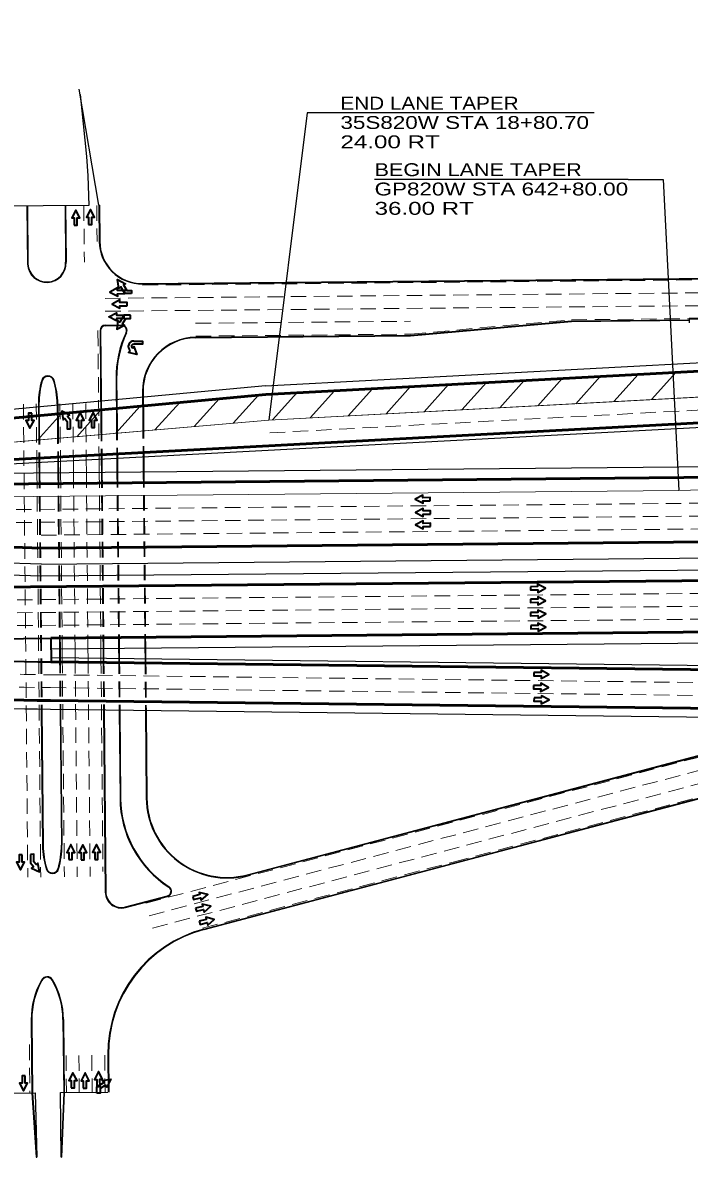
# Model space of a CAD drawing. Extents: x 2326434 to 2368642, y 6985225 to 6995090.
# Drawn here: x 2330793 to 2331414, y 6990716 to 6991772 of the extents above; entities that cross this region are included whole.
import ezdxf

# ---------------------------------------------------------------- set-up
doc = ezdxf.new("R2010")
doc.units = 0
doc.header["$LTSCALE"] = 4.8
doc.linetypes.add('MEDIUM_DASHED', pattern=[4.5, 3, -1.5])
for name, color, linetype, lineweight in [('10', 7, 'Continuous', 35), ('26', 7, 'Continuous', 25), ('27', 7, 'Continuous', 25), ('28', 7, 'Continuous', 25), ('40', 7, 'Continuous', 35), ('5', 7, 'Continuous', 25), ('50', 7, 'MEDIUM_DASHED', 13)]:
    doc.layers.add(name, color=color, linetype=linetype, lineweight=lineweight)

msp = doc.modelspace()

# ---------------------------------------------------------------- linework, layer by layer
at = {"layer": '10'}
for p, q in [((2330426.072, 6991195.246), (2330819.65, 6991198.923)), ((2330819.65, 6991198.923), (2330819.856, 6991176.858))]:
    msp.add_line(p, q, dxfattribs=at)
for centre, radius, start, end in [((2331921.237, 6992748.984), 1265.239, 273.05017, 273.05017), ((2330888.37, 6996870.024), 5693.578, 265.34266, 269.30964)]:
    msp.add_arc(centre, radius, start, end, dxfattribs=at)
at = {"layer": '26'}
for p, q in [((2330723.193, 6991352.028), (2332252.211, 6991366.314)), ((2330810.967, 6991256.844), (2332091.911, 6991268.812)), ((2330819.743, 6991188.923), (2332235.248, 6991202.148))]:
    msp.add_line(p, q, dxfattribs=at)
at = {"layer": '26', "lineweight": 53}
for p, q in [((2330723.287, 6991342.029), (2332252.305, 6991356.314)), ((2330686.071, 6991245.677), (2332092.005, 6991258.812)), ((2330819.65, 6991198.923), (2332235.154, 6991212.148))]:
    msp.add_line(p, q, dxfattribs=at)
at = {"layer": '27'}
for p, q in [((2331413.972, 6991496.376), (2331414.01, 6991492.377)), ((2331019.444, 6991433.897), (2331988.561, 6991485.537)), ((2330723.061, 6991358.019), (2332517.722, 6991453.649)), ((2331019.444, 6991433.897), (2330720.507, 6991405.951)), ((2330819.818, 6991180.859), (2332703.156, 6991158.166))]:
    msp.add_line(p, q, dxfattribs=at)
at = {"layer": '27', "lineweight": 53}
for p, q in [((2331019.869, 6991425.908), (2331988.987, 6991477.549)), ((2330723.1, 6991362.027), (2332517.509, 6991457.643)), ((2330720.933, 6991397.962), (2331019.869, 6991425.908)), ((2330819.77, 6991176.859), (2332703.108, 6991154.166)), ((2330819.337, 6991140.862), (2331786.164, 6991129.212))]:
    msp.add_line(p, q, dxfattribs=at)
at = {"layer": '27'}
msp.add_lwpolyline([(2330819.23, 6991132.863), (2331565.86, 6991123.866), (2331786.067, 6991121.213)], dxfattribs=at)
at = {"layer": '27', "lineweight": 40}
msp.add_arc((2331440.616, 6988645.712), 2850.789, 83.98494, 90.53549, dxfattribs=at)
at = {"layer": '27', "lineweight": 53}
msp.add_arc((2330888.37, 6996870.024), 5729.578, 265.33564, 269.30964, dxfattribs=at)
at = {"layer": '27'}
msp.add_arc((2330888.37, 6996870.024), 5737.578, 265.48726, 269.30964, dxfattribs=at)
at = {"layer": '28'}
for p, q in [((2330864.386, 6991601.901), (2330846.071, 6991710.103)), ((2330854.998, 6991601.813), (2330764.308, 6991600.966)), ((2330797.388, 6991601.275), (2330797.893, 6991547.239)), ((2330797.888, 6991601.28), (2330798.393, 6991547.243)), ((2330832.887, 6991601.607), (2330833.379, 6991548.944)), ((2330833.387, 6991601.611), (2330833.879, 6991548.949)), ((2330864.885, 6991601.906), (2330864.386, 6991601.901)), ((2330864.386, 6991601.901), (2330864.7, 6991568.246)), ((2330864.885, 6991601.906), (2330865.2, 6991568.251)), ((2330905.067, 6991529.122), (2331710.807, 6991536.652)), ((2330905.072, 6991528.622), (2331710.811, 6991536.152)), ((2331304.39, 6991494.352), (2331413.982, 6991495.376)), ((2331304.414, 6991493.852), (2331413.986, 6991494.876)), ((2330865.476, 6991485.25), (2330866.303, 6991396.692)), ((2330865.976, 6991485.254), (2330866.803, 6991396.722)), ((2330870.429, 6991490.296), (2330885.56, 6991490.438)), ((2330870.433, 6991489.796), (2330885.564, 6991489.938)), ((2331154.508, 6991480.951), (2331304.39, 6991494.352)), ((2331154.533, 6991480.451), (2331304.414, 6991493.852)), ((2330954.537, 6991479.082), (2331154.508, 6991480.951)), ((2330954.542, 6991478.582), (2331154.533, 6991480.451)), ((2330880.396, 6991440.387), (2330880.796, 6991397.58)), ((2330880.896, 6991440.392), (2330881.295, 6991397.611)), ((2330905.007, 6991428.617), (2330905.282, 6991399.164)), ((2330905.507, 6991428.621), (2330905.782, 6991399.169)), ((2330808.11, 6991417.049), (2330808.33, 6991393.51)), ((2330808.61, 6991417.054), (2330808.83, 6991393.535)), ((2330825.61, 6991417.213), (2330825.823, 6991394.408)), ((2330826.11, 6991417.217), (2330826.323, 6991394.434)), ((2330808.62, 6991362.578), (2330808.711, 6991352.827)), ((2330809.119, 6991362.605), (2330809.211, 6991352.832)), ((2330826.112, 6991363.51), (2330826.21, 6991352.991)), ((2330826.612, 6991363.537), (2330826.71, 6991352.996)), ((2330866.593, 6991365.667), (2330866.708, 6991353.369)), ((2330867.093, 6991365.694), (2330867.208, 6991353.374)), ((2330881.087, 6991366.439), (2330881.208, 6991353.505)), ((2330881.586, 6991366.466), (2330881.707, 6991353.509)), ((2330905.576, 6991367.744), (2330905.706, 6991353.734)), ((2330906.075, 6991367.771), (2330906.206, 6991353.738)), ((2330810.865, 6991267.844), (2330385.724, 6991280.873)), ((2330810.865, 6991267.844), (2331441.837, 6991273.739)), ((2330385.827, 6991269.873), (2330810.967, 6991256.844)), ((2330827.743, 6991188.998), (2330827.82, 6991180.763)), ((2330828.243, 6991189.003), (2330828.32, 6991180.757)), ((2330868.241, 6991189.376), (2330868.326, 6991180.275)), ((2330868.741, 6991189.381), (2330868.826, 6991180.269)), ((2330882.74, 6991189.512), (2330882.828, 6991180.1)), ((2330883.24, 6991189.517), (2330883.328, 6991180.094)), ((2330907.239, 6991189.741), (2330907.332, 6991179.805)), ((2330907.739, 6991189.745), (2330907.832, 6991179.799)), ((2330810.765, 6991132.983), (2330811.953, 6991005.934)), ((2330811.265, 6991132.976), (2330812.453, 6991005.939)), ((2330828.268, 6991132.755), (2330829.452, 6991006.097)), ((2330828.768, 6991132.749), (2330829.952, 6991006.102)), ((2330868.774, 6991132.266), (2330870.361, 6990962.531)), ((2330869.275, 6991132.26), (2330870.861, 6990962.536)), ((2330883.277, 6991132.091), (2330884.046, 6991049.749)), ((2330883.777, 6991132.085), (2330884.546, 6991049.754)), ((2330907.781, 6991131.796), (2330908.545, 6991049.978)), ((2330908.281, 6991131.79), (2330909.045, 6991049.983)), ((2331002.577, 6990978.652), (2331426.947, 6991090.806)), ((2331002.705, 6990978.169), (2331427.074, 6991090.322)), ((2331194.544, 6990989.047), (2331436.911, 6991053.1)), ((2330962.238, 6990927.652), (2331194.544, 6990989.047)), ((2330889.065, 6990948.653), (2330928.215, 6990958.999)), ((2330889.193, 6990948.169), (2330928.343, 6990958.516)), ((2330801.47, 6990843.524), (2330802.105, 6990775.581)), ((2330801.97, 6990843.529), (2330802.605, 6990775.586)), ((2330830.969, 6990843.8), (2330831.604, 6990775.868)), ((2330831.469, 6990843.805), (2330832.104, 6990775.873)), ((2330872.777, 6990810.997), (2330873.101, 6990776.272)), ((2330873.277, 6990811.002), (2330873.601, 6990776.277)), ((2330802.105, 6990775.581), (2330806.065, 6990715.617)), ((2330802.604, 6990775.614), (2330806.565, 6990715.622)), ((2330828.775, 6990775.841), (2330872.601, 6990776.267)), ((2330829.181, 6990715.867), (2330828.775, 6990775.841)), ((2330831.604, 6990775.893), (2330829.181, 6990715.867)), ((2330832.104, 6990775.873), (2330829.68, 6990715.847)), ((2330806.065, 6990715.617), (2330806.565, 6990715.622)), ((2330829.18, 6990715.842), (2330829.68, 6990715.847))]:
    msp.add_line(p, q, dxfattribs=at)
at = {"layer": '28', "linetype": 'MEDIUM_DASHED'}
for p, q in [((2330808.33, 6991393.51), (2330808.62, 6991362.578)), ((2330808.83, 6991393.535), (2330809.119, 6991362.605)), ((2330825.823, 6991394.408), (2330826.112, 6991363.51)), ((2330826.323, 6991394.434), (2330826.612, 6991363.537)), ((2330866.303, 6991396.692), (2330866.593, 6991365.667)), ((2330866.803, 6991396.722), (2330867.093, 6991365.694)), ((2330880.796, 6991397.58), (2330881.087, 6991366.439)), ((2330881.295, 6991397.611), (2330881.586, 6991366.466)), ((2330905.282, 6991399.164), (2330905.576, 6991367.744)), ((2330905.782, 6991399.197), (2330906.075, 6991367.771)), ((2330808.711, 6991352.827), (2330810.765, 6991132.983)), ((2330809.211, 6991352.832), (2330811.265, 6991132.976)), ((2330826.21, 6991352.991), (2330827.743, 6991188.998)), ((2330826.71, 6991352.996), (2330828.243, 6991189.003)), ((2330866.708, 6991353.369), (2330868.241, 6991189.376)), ((2330867.208, 6991353.374), (2330868.741, 6991189.381)), ((2330881.208, 6991353.505), (2330882.74, 6991189.512)), ((2330881.707, 6991353.509), (2330883.24, 6991189.517)), ((2330905.706, 6991353.734), (2330907.239, 6991189.741)), ((2330906.206, 6991353.738), (2330907.739, 6991189.745)), ((2330827.82, 6991180.763), (2330828.268, 6991132.755)), ((2330828.32, 6991180.757), (2330828.768, 6991132.749)), ((2330868.326, 6991180.275), (2330868.774, 6991132.266)), ((2330868.826, 6991180.269), (2330869.275, 6991132.26)), ((2330882.828, 6991180.1), (2330883.277, 6991132.091)), ((2330883.328, 6991180.094), (2330883.777, 6991132.085)), ((2330907.332, 6991179.805), (2330907.781, 6991131.796)), ((2330907.832, 6991179.799), (2330908.281, 6991131.79))]:
    msp.add_line(p, q, dxfattribs=at)
at = {"layer": '28', "lineweight": 53}
msp.add_line((2330810.724, 6991282.843), (2330510.625, 6991292.04), dxfattribs=at)
at = {"layer": '28'}
for points in [[(2330846.906, 6991705.171), (2330852.935, 6991647.371), (2330853.974, 6991629.26), (2330854.998, 6991601.813)], [(2330962.11, 6990928.135), (2331194.416, 6990989.53), (2331436.784, 6991053.584)], [(2330773.606, 6990775.304), (2330805.132, 6990775.611), (2330806.565, 6990715.622)]]:
    msp.add_lwpolyline(points, dxfattribs=at)
at = {"layer": '28', "lineweight": 53}
msp.add_lwpolyline([(2330810.724, 6991282.843), (2331791.682, 6991292.008), (2332091.556, 6991306.81)], dxfattribs=at)
at = {"layer": '28'}
for centre, radius, start, end in [((2330904.698, 6991568.62), 40, 180.53544, 270.53549), ((2330904.698, 6991568.62), 39.5, 180.53544, 270.53549), ((2330815.872, 6991548.093), 18, 182.78276, 2.78276), ((2330815.872, 6991548.093), 17.5, 182.78276, 2.78276), ((2330870.475, 6991485.296), 5, 90.53549, 180.53544), ((2330870.475, 6991485.296), 4.5, 90.53549, 180.53544), ((2330885.606, 6991485.438), 5, 335.15854, 90.53549), ((2330885.606, 6991485.438), 4.5, 335.15854, 90.53549), ((2330980.891, 6991441.326), 100.5, 155.15854, 180.53544), ((2330980.891, 6991441.326), 100, 155.15854, 180.53544), ((2330955.004, 6991429.084), 50, 90.53549, 180.53544), ((2330955.004, 6991429.084), 49.5, 90.53549, 180.53544), ((2330816.918, 6991437.184), 6, 17.50561, 163.59031), ((2330816.918, 6991437.184), 5.5, 17.50561, 163.59031), ((2330883.108, 6991417.691), 75, 163.59031, 180.49039), ((2330883.108, 6991417.691), 74.5, 163.59031, 180.49039), ((2330751.114, 6991416.429), 74.5, 0.58018, 17.50561), ((2330751.114, 6991416.429), 75, 0.58018, 17.50561), ((2330983.542, 6991050.679), 99.5, 180.53544, 237.10882), ((2330983.542, 6991050.679), 99, 180.53544, 237.10882), ((2330983.542, 6991050.679), 75, 180.53544, 284.80383), ((2330983.542, 6991050.679), 74.5, 180.53544, 284.80383), ((2330886.949, 6991006.634), 75, 180.53512, 197.49281), ((2330886.949, 6991006.634), 74.5, 180.53512, 197.49281), ((2330754.955, 6991005.401), 74.5, 343.5777, 0.53544), ((2330754.955, 6991005.401), 75, 343.5777, 0.53544), ((2330821.14, 6990985.894), 6, 197.49281, 343.5777), ((2330821.14, 6990985.894), 5.5, 197.49281, 343.5777), ((2330927.065, 6990963.35), 4.5, 284.80383, 57.10882), ((2330927.065, 6990963.35), 5, 284.80383, 57.10882), ((2330885.36, 6990962.671), 15, 180.53544, 284.80383), ((2330885.36, 6990962.671), 14.5, 180.53544, 284.80383), ((2330992.772, 6990812.119), 120, 104.80383, 180.53544), ((2330992.772, 6990812.119), 119.5, 104.80383, 180.53544), ((2330816.135, 6990877.707), 6, 30.15527, 150.97153), ((2330816.135, 6990877.707), 5.5, 30.15527, 150.97153), ((2330876.467, 6990844.225), 75, 150.97153, 180.53544), ((2330876.467, 6990844.225), 74.5, 150.97153, 180.53544), ((2330756.473, 6990843.045), 74.5, 0.58018, 30.15527), ((2330756.473, 6990843.045), 75, 0.58018, 30.15527)]:
    msp.add_arc(centre, radius, start, end, dxfattribs=at)
at = {"layer": '40'}
for points in [[(2330841.307, 6991583.527), (2330844.308, 6991583.527), (2330844.308, 6991590.334), (2330846.745, 6991590.334), (2330842.966, 6991597.534), (2330839.187, 6991590.334), (2330841.307, 6991590.334)], [(2330854.848, 6991584.034), (2330857.849, 6991584.034), (2330857.849, 6991590.84), (2330860.286, 6991590.84), (2330856.507, 6991598.04), (2330852.728, 6991590.84), (2330854.848, 6991590.84)], [(2330894.652, 6991519.716), (2330888.668, 6991519.695), (2330884.811, 6991526.054), (2330882.805, 6991524.669), (2330881.825, 6991532.742), (2330889.025, 6991528.963), (2330887.281, 6991527.759), (2330890.425, 6991522.669), (2330894.603, 6991522.745)], [(2330888.668, 6991519.695), (2330888.601, 6991522.695), (2330881.796, 6991522.543), (2330881.742, 6991524.98), (2330874.627, 6991521.041), (2330881.91, 6991517.424), (2330881.863, 6991519.543)], [(2330890.715, 6991508.387), (2330890.713, 6991511.388), (2330883.906, 6991511.383), (2330883.904, 6991513.82), (2330876.707, 6991510.037), (2330883.909, 6991506.263), (2330883.908, 6991508.382)], [(2330887.681, 6991499.626), (2330887.671, 6991496.625), (2330880.864, 6991496.65), (2330880.855, 6991494.212), (2330873.669, 6991498.017), (2330880.882, 6991501.77), (2330880.875, 6991499.65)], [(2330893.665, 6991499.716), (2330887.681, 6991499.626), (2330883.944, 6991493.196), (2330881.913, 6991494.543), (2330881.083, 6991486.454), (2330888.212, 6991490.366), (2330886.445, 6991491.538), (2330889.494, 6991496.685), (2330893.673, 6991496.688)], [(2330801.878, 6991408.46), (2330798.877, 6991408.46), (2330798.877, 6991401.653), (2330796.44, 6991401.653), (2330800.219, 6991394.453), (2330803.998, 6991401.653), (2330801.878, 6991401.653)], [(2330838.005, 6991393.883), (2330837.908, 6991401.826), (2330835.147, 6991405.234), (2330837.1, 6991406.692), (2330829.765, 6991410.202), (2330831.044, 6991402.171), (2330832.742, 6991403.439), (2330834.92, 6991400.751), (2330835.005, 6991393.846)], [(2330845.291, 6991395.043), (2330848.291, 6991395.043), (2330848.291, 6991401.849), (2330850.729, 6991401.849), (2330846.95, 6991409.05), (2330843.171, 6991401.849), (2330845.291, 6991401.849)], [(2330857.434, 6991395.031), (2330860.435, 6991395.031), (2330860.435, 6991401.837), (2330862.872, 6991401.837), (2330859.093, 6991409.037), (2330855.314, 6991401.837), (2330857.434, 6991401.837)], [(2331172.901, 6991326.836), (2331172.852, 6991329.836), (2331166.046, 6991329.724), (2331166.006, 6991332.161), (2331158.869, 6991328.264), (2331166.13, 6991324.604), (2331166.095, 6991326.723)], [(2331173.038, 6991314.452), (2331172.989, 6991317.452), (2331166.183, 6991317.34), (2331166.143, 6991319.777), (2331159.006, 6991315.879), (2331166.268, 6991312.22), (2331166.233, 6991314.339)], [(2331173.115, 6991302.865), (2331173.065, 6991305.865), (2331166.259, 6991305.753), (2331166.219, 6991308.19), (2331159.082, 6991304.293), (2331166.344, 6991300.634), (2331166.309, 6991302.753)], [(2331266.034, 6991246.823), (2331266.086, 6991243.823), (2331272.892, 6991243.941), (2331272.935, 6991241.505), (2331280.068, 6991245.408), (2331272.803, 6991249.061), (2331272.84, 6991246.942)], [(2331266.121, 6991235.237), (2331266.173, 6991232.237), (2331272.979, 6991232.355), (2331273.021, 6991229.918), (2331280.155, 6991233.822), (2331272.89, 6991237.475), (2331272.927, 6991235.355)], [(2331266.27, 6991222.853), (2331266.322, 6991219.852), (2331273.128, 6991219.971), (2331273.17, 6991217.534), (2331280.303, 6991221.438), (2331273.038, 6991225.091), (2331273.075, 6991222.971)], [(2331266.371, 6991210.739), (2331266.423, 6991207.739), (2331273.229, 6991207.858), (2331273.272, 6991205.421), (2331280.405, 6991209.324), (2331273.14, 6991212.977), (2331273.177, 6991210.858)], [(2331269.245, 6991167.006), (2331269.19, 6991164.005), (2331275.996, 6991163.881), (2331275.951, 6991161.444), (2331283.219, 6991165.091), (2331276.089, 6991169.001), (2331276.05, 6991166.882)], [(2331268.914, 6991154.896), (2331268.86, 6991151.896), (2331275.665, 6991151.772), (2331275.621, 6991149.335), (2331282.889, 6991152.982), (2331275.759, 6991156.891), (2331275.72, 6991154.772)], [(2331269.453, 6991143.364), (2331269.399, 6991140.363), (2331276.204, 6991140.239), (2331276.16, 6991137.802), (2331283.428, 6991141.449), (2331276.298, 6991145.359), (2331276.259, 6991143.24)], [(2330836.542, 6990992.738), (2330839.543, 6990992.738), (2330839.543, 6990999.545), (2330841.98, 6990999.545), (2330838.202, 6991006.745), (2330834.423, 6990999.545), (2330836.542, 6990999.545)], [(2330847.792, 6990992.65), (2330850.793, 6990992.65), (2330850.793, 6990999.457), (2330853.23, 6990999.457), (2330849.451, 6991006.657), (2330845.672, 6990999.457), (2330847.792, 6990999.457)], [(2330860.497, 6990992.87), (2330863.498, 6990992.87), (2330863.498, 6990999.676), (2330865.935, 6990999.676), (2330862.157, 6991006.877), (2330858.378, 6990999.676), (2330860.497, 6990999.676)], [(2330793.116, 6990997.343), (2330790.115, 6990997.343), (2330790.115, 6990990.537), (2330787.678, 6990990.537), (2330791.457, 6990983.337), (2330795.235, 6990990.537), (2330793.116, 6990990.537)], [(2330800.713, 6990997.653), (2330800.81, 6990989.71), (2330803.571, 6990986.302), (2330801.617, 6990984.844), (2330808.952, 6990981.334), (2330807.674, 6990989.365), (2330805.976, 6990988.097), (2330803.798, 6990990.785), (2330803.713, 6990997.69)], [(2330951.78, 6990958.519), (2330952.516, 6990955.61), (2330959.115, 6990957.281), (2330959.713, 6990954.918), (2330965.765, 6990960.349), (2330957.858, 6990962.245), (2330958.378, 6990960.19)], [(2330954.456, 6990947.592), (2330955.193, 6990944.683), (2330961.791, 6990946.354), (2330962.389, 6990943.991), (2330968.442, 6990949.422), (2330960.534, 6990951.318), (2330961.055, 6990949.263)], [(2330957.788, 6990935.329), (2330958.524, 6990932.42), (2330965.123, 6990934.091), (2330965.721, 6990931.728), (2330971.773, 6990937.159), (2330963.866, 6990939.055), (2330964.386, 6990937)], [(2330795.861, 6990791.566), (2330792.861, 6990791.566), (2330792.861, 6990784.759), (2330790.423, 6990784.759), (2330794.202, 6990777.559), (2330797.981, 6990784.759), (2330795.861, 6990784.759)], [(2330838.611, 6990780.219), (2330841.612, 6990780.219), (2330841.612, 6990787.026), (2330844.049, 6990787.026), (2330840.271, 6990794.226), (2330836.492, 6990787.026), (2330838.611, 6990787.026)], [(2330849.861, 6990780.132), (2330852.862, 6990780.132), (2330852.862, 6990786.938), (2330855.299, 6990786.938), (2330851.52, 6990794.139), (2330847.741, 6990786.938), (2330849.861, 6990786.938)], [(2330862.554, 6990781.376), (2330865.554, 6990781.446), (2330865.395, 6990788.251), (2330867.832, 6990788.308), (2330863.887, 6990795.418), (2330860.277, 6990788.132), (2330862.396, 6990788.181)], [(2330862.581, 6990775.392), (2330862.554, 6990781.376), (2330868.909, 6990785.239), (2330867.523, 6990787.244), (2330875.594, 6990788.232), (2330871.822, 6990781.028), (2330870.616, 6990782.772), (2330865.53, 6990779.622), (2330865.61, 6990775.444)]]:
    msp.add_lwpolyline(points, close=True, dxfattribs=at)
for points in [[(2330897.033, 6991475.575), (2330904.977, 6991475.575), (2330904.977, 6991472.574), (2330896.817, 6991472.574), (2330896.867, 6991472.572)], [(2330895.53, 6991469.02), (2330896.93, 6991470.6), (2330899.815, 6991462.997), (2330891.919, 6991464.942), (2330893.535, 6991466.767)]]:
    msp.add_lwpolyline(points, dxfattribs=at)
for radius, end in [(4.997, 229.84499), (1.989, 231.9188)]:
    msp.add_arc((2330896.757, 6991470.586), radius, 86.84016, end, dxfattribs=at)
at = {"layer": '5'}
for p, q in [((2331325.43, 6991688.013), (2331089.275, 6991688.013)), ((2331357.221, 6991626.082), (2331121.066, 6991626.082))]:
    msp.add_line(p, q, dxfattribs=at)
for points in [[(2331089.275, 6991688.013), (2331058.416, 6991688.013), (2331022.739, 6991402.027)], [(2331357.221, 6991626.082), (2331389.752, 6991626.082), (2331404.275, 6991336.391)]]:
    msp.add_lwpolyline(points, dxfattribs=at)
at = {"layer": '50'}
for p, q in [((2330850.387, 6991601.77), (2330850.879, 6991549.107)), ((2330862.386, 6991601.882), (2330862.7, 6991568.227)), ((2330905.081, 6991527.622), (2331710.821, 6991535.152)), ((2330870.195, 6991515.295), (2331710.933, 6991523.153)), ((2330870.307, 6991503.296), (2331520.884, 6991509.376)), ((2331154.459, 6991481.95), (2331304.34, 6991495.352)), ((2331304.34, 6991495.352), (2331413.972, 6991496.376)), ((2330863.476, 6991485.231), (2330864.594, 6991365.561)), ((2330954.416, 6991492.081), (2331154.407, 6991493.95)), ((2330954.528, 6991480.082), (2331154.459, 6991481.95)), ((2331023.378, 6991390.044), (2331984.093, 6991441.237)), ((2330794.111, 6991416.918), (2330798.229, 6990976.336)), ((2330806.11, 6991417.031), (2330806.62, 6991362.471)), ((2330828.11, 6991417.236), (2330828.611, 6991363.643)), ((2330840.109, 6991417.348), (2330840.605, 6991364.282)), ((2330852.109, 6991417.46), (2330852.6, 6991364.921)), ((2330828.611, 6991363.643), (2330828.71, 6991353.014)), ((2330840.605, 6991364.282), (2330840.709, 6991353.126)), ((2330852.6, 6991364.921), (2330852.709, 6991353.238)), ((2330864.594, 6991365.561), (2330864.708, 6991353.351)), ((2330828.71, 6991353.014), (2330830.243, 6991189.021)), ((2330840.709, 6991353.126), (2330842.242, 6991189.133)), ((2330852.709, 6991353.238), (2330854.242, 6991189.246)), ((2330864.708, 6991353.351), (2330866.241, 6991189.358)), ((2329664.221, 6991308.133), (2332252.529, 6991332.315)), ((2329664.333, 6991296.134), (2332252.641, 6991320.316)), ((2330810.612, 6991294.843), (2331791.57, 6991304.008)), ((2329665.118, 6991212.137), (2332253.426, 6991236.319)), ((2329665.23, 6991200.138), (2332253.538, 6991224.32)), ((2330819.615, 6991164.86), (2332702.963, 6991142.167)), ((2330819.471, 6991152.861), (2331786.308, 6991141.211)), ((2330908.1, 6990952.132), (2331427.33, 6991089.355)), ((2330911.166, 6990940.53), (2331430.396, 6991077.754)), ((2330914.232, 6990928.928), (2331433.462, 6991066.152)), ((2331194.161, 6990990.497), (2331436.528, 6991054.55)), ((2330960.857, 6990928.839), (2331201.365, 6990992.401)), ((2330799.684, 6990820.601), (2330800.105, 6990775.562)), ((2330833.781, 6990810.379), (2330834.104, 6990775.893)), ((2330845.78, 6990810.491), (2330846.103, 6990776.009)), ((2330857.78, 6990810.603), (2330858.103, 6990776.126)), ((2330869.779, 6990810.715), (2330870.101, 6990776.243))]:
    msp.add_line(p, q, dxfattribs=at)
at = {"layer": '50', "linetype": 'Continuous'}
for p, q in [((2331022.739, 6991402.027), (2331911.828, 6991449.403)), ((2331308.306, 6991417.244), (2331330.995, 6991442.487)), ((2331343.612, 6991419.125), (2331366.301, 6991444.368)), ((2331378.917, 6991421.006), (2331401.606, 6991446.249)), ((2331131.78, 6991407.838), (2331154.469, 6991433.081)), ((2331167.085, 6991409.719), (2331189.774, 6991434.962)), ((2331202.391, 6991411.6), (2331225.08, 6991436.843)), ((2331237.696, 6991413.481), (2331260.385, 6991438.724)), ((2331273.001, 6991415.363), (2331295.69, 6991440.606)), ((2330953.061, 6991395.991), (2330976.289, 6991421.834)), ((2330989.514, 6991399.149), (2331012.987, 6991425.265)), ((2331025.864, 6991402.194), (2331048.553, 6991427.437)), ((2331061.17, 6991404.075), (2331083.859, 6991429.318)), ((2331096.475, 6991405.956), (2331119.164, 6991431.199)), ((2330843.704, 6991386.518), (2330866.195, 6991411.542)), ((2330880.156, 6991389.676), (2330902.893, 6991414.973)), ((2330916.609, 6991392.834), (2330939.591, 6991418.404)), ((2331022.739, 6991402.027), (2330722.355, 6991376.007)), ((2330807.251, 6991383.361), (2330829.497, 6991408.111)), ((2331404.275, 6991336.391), (2332124.131, 6991355.117)), ((2330723.399, 6991330.029), (2331404.275, 6991336.391))]:
    msp.add_line(p, q, dxfattribs=at)
for points in [[(2331988.987, 6991477.549), (2331019.869, 6991425.908), (2330720.933, 6991397.962), (2330392.434, 6991380.458)], [(2330074.514, 6991341.486), (2330722.355, 6991376.007), (2331022.739, 6991402.027), (2331911.828, 6991449.403)]]:
    msp.add_lwpolyline(points, dxfattribs=at)
at = {"layer": '50'}
for points in [[(2330806.62, 6991362.471), (2330806.711, 6991352.809), (2330810.228, 6990976.448)], [(2329665.005, 6991224.137), (2332090.455, 6991246.797), (2332253.314, 6991248.319)], [(2330830.243, 6991189.021), (2330830.32, 6991180.733), (2330832.227, 6990976.697)], [(2330842.242, 6991189.133), (2330842.322, 6991180.588), (2330844.226, 6990976.809)], [(2330854.242, 6991189.246), (2330854.324, 6991180.443), (2330856.226, 6990976.921)], [(2330866.241, 6991189.358), (2330866.325, 6991180.299), (2330868.18, 6990981.804)]]:
    msp.add_lwpolyline(points, dxfattribs=at)
for radius in [5705.578, 5717.578]:
    msp.add_arc((2330888.37, 6996870.024), radius, 265.33564, 269.30964, dxfattribs=at)

# ---------------------------------------------------------------- texts
at = {"layer": '5'}
for s, width, p in [('END LANE TAPER', 1.2, (2331089.275, 6991691.013)), ('35S820W STA 18+80.70', 1.3, (2331089.275, 6991673.013)), ('24.00 RT', 1.4, (2331089.275, 6991655.013)), ('BEGIN LANE TAPER', 1.25, (2331121.067, 6991629.082)), ('GP820W STA 642+80.00', 1.3, (2331121.067, 6991611.082)), ('36.00 RT', 1.4, (2331121.067, 6991593.082))]:
    msp.add_text(s, height=12, dxfattribs=dict(at, width=width)).set_placement(p)

doc.saveas('drawing.dxf')
